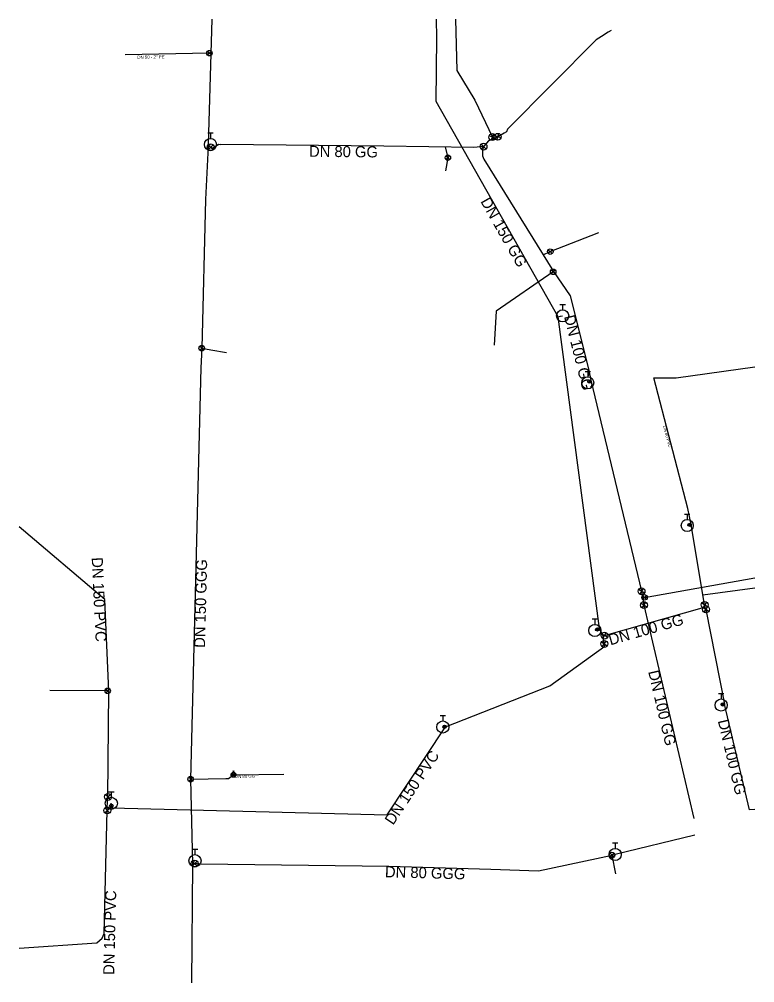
# Model space of a CAD drawing. Extents: x -464830 to -464723, y -1094758 to -1094618.
import ezdxf

# ---------------------------------------------------------------- set-up
doc = ezdxf.new("R2010")
doc.units = 0
for name, color, linetype in [('_hydrantova_odbocka_', 7, 'Continuous'), ('_pripojka_prevzato_z_dokumentace_', 7, 'Continuous'), ('_pripojka_priblizne_', 7, 'Continuous'), ('_voda_smvak_prevzato_z_dokumentace_', 7, 'Continuous'), ('_voda_smvak_priblizne_', 7, 'Continuous'), ('Default', 7, 'Continuous'), ('MoLevel 2', 7, 'Continuous'), ('MoLevel 27', 7, 'Continuous'), ('MoLevel 28', 7, 'Continuous'), ('MoLevel 30', 7, 'Continuous'), ('MoLevel 32', 7, 'Continuous'), ('MoLevel 42', 7, 'Continuous'), ('MoLevel 46', 7, 'Continuous'), ('MoLevel 53', 7, 'Continuous')]:
    doc.layers.add(name, color=color, linetype=linetype)

# ---------------------------------------------------------------- blocks, each defined once
blk = doc.blocks.new('_uzaver_')
at = {"layer": 'Default'}
for p, q in [((-0.000035, -0.000035), (0.000035, 0.000035)), ((0.000035, -0.000035), (-0.000035, 0.000035))]:
    blk.add_line(p, q, dxfattribs=at)
for radius in [0.00005, 0.0000025]:
    blk.add_circle((0, 0), radius, dxfattribs=at)
blk = doc.blocks.new('_uzaver_pripojka_')
at = {"layer": 'Default'}
for p, q in [((-0.000035, -0.000035), (0.000035, 0.000035)), ((0.000035, -0.000035), (-0.000035, 0.000035))]:
    blk.add_line(p, q, dxfattribs=at)
for radius in [0.00005, 0.0000025]:
    blk.add_circle((0, 0), radius, dxfattribs=at)
blk = doc.blocks.new('_hydrant_voda_')
at = {"layer": 'Default'}
for p, q in [((-0.0000225, 0.000095), (0.0000225, 0.000095)), ((0, 0.000095), (0, 0.00005))]:
    blk.add_line(p, q, dxfattribs=at)
blk.add_circle((0, 0), 0.00005, dxfattribs=at)
blk = doc.blocks.new('_sachta_voda_')
at = {"layer": 'Default'}
blk.add_lwpolyline([(-0.00001, 0.000065), (0, 0.000035), (0.00001, 0.000065)], dxfattribs=at)
blk.add_circle((0, 0), 0.000035, dxfattribs=at)
blk = doc.blocks.new('_poklop_voda_')
at = {"layer": 'Default'}
blk.add_circle((0, 0), 0.00002, dxfattribs=at)

msp = doc.modelspace()

# ---------------------------------------------------------------- linework, layer by layer
at = {"layer": '_hydrantova_odbocka_'}
msp.add_line((-464802.46, -1094635.81), (-464802.15, -1094635.8), dxfattribs=at)
for points in [[(-464751.57, -1094660.85), (-464751.25, -1094660.77), (-464750.94, -1094660.71)], [(-464746.83, -1094670.06), (-464747.04, -1094670.25), (-464747.29, -1094670.45)], [(-464732.27, -1094691.01), (-464732.47, -1094691.07), (-464732.82, -1094691.18)], [(-464745.6, -1094706.12), (-464745.89, -1094706.27), (-464746.27, -1094706.43)], [(-464727.43, -1094717.11), (-464727.66, -1094717.17), (-464727.89, -1094717.26)], [(-464767.97, -1094720.43), (-464768.1, -1094720.41), (-464768.35, -1094720.45)], [(-464816.52, -1094732.2), (-464816.55, -1094731.91), (-464816.56, -1094731.54)], [(-464804.77, -1094739.9), (-464804.6, -1094739.89), (-464804.39, -1094739.88)]]:
    msp.add_lwpolyline(points, dxfattribs=at)
at = {"layer": '_pripojka_prevzato_z_dokumentace_'}
for p, q in [((-464802.29, -1094622.54), (-464802.09, -1094622.54)), ((-464803.41, -1094665.4), (-464802.11, -1094665.65)), ((-464743.77, -1094739.06), (-464743.25, -1094741.78))]:
    msp.add_line(p, q, dxfattribs=at)
msp.add_lwpolyline([(-464805.03, -1094728.01), (-464799.93, -1094727.91), (-464799.54, -1094727.91)], dxfattribs=at)
at = {"layer": '_pripojka_priblizne_'}
for p, q in [((-464802.29, -1094622.54), (-464814.54, -1094622.79)), ((-464802.11, -1094665.65), (-464799.8, -1094666.01)), ((-464730.54, -1094701.23), (-464723.01, -1094700.24)), ((-464799.54, -1094727.91), (-464798.79, -1094727.4))]:
    msp.add_line(p, q, dxfattribs=at)
for points in [[(-464768.01, -1094636.16), (-464767.62, -1094637.72), (-464767.96, -1094639.65)], [(-464753.76, -1094651.85), (-464752.74, -1094651.37), (-464745.68, -1094648.61)], [(-464752.26, -1094654.26), (-464752.32, -1094654.31), (-464760.58, -1094660.02), (-464760.88, -1094664.97)], [(-464732.27, -1094691.01), (-464732.76, -1094688.69), (-464737.68, -1094669.72), (-464734.43, -1094669.72), (-464723.01, -1094668.09)], [(-464739.27, -1094701.68), (-464739.03, -1094701.62), (-464723.01, -1094698.77)], [(-464816.9, -1094715.24), (-464817.08, -1094715.19), (-464825.5, -1094715.14)], [(-464798.79, -1094727.4), (-464798.79, -1094727.4), (-464791.46, -1094727.31)]]:
    msp.add_lwpolyline(points, dxfattribs=at)
at = {"layer": '_voda_smvak_prevzato_z_dokumentace_'}
for p, q in [((-464761.14, -1094634.75), (-464761.06, -1094635.01)), ((-464802.47, -1094636.03), (-464802.12, -1094636.21)), ((-464762.37, -1094636.1), (-464762.44, -1094636.11)), ((-464745.6, -1094706.12), (-464751.57, -1094660.85)), ((-464746.83, -1094670.06), (-464739.47, -1094700.73)), ((-464739.47, -1094700.73), (-464739.27, -1094701.68)), ((-464739.27, -1094701.68), (-464739.12, -1094702.74)), ((-464739.12, -1094702.74), (-464731.88, -1094733.73)), ((-464745.04, -1094707.24), (-464745.6, -1094706.12)), ((-464817.14, -1094732.16), (-464817.05, -1094730.62)), ((-464817.14, -1094732.57), (-464817.14, -1094732.16)), ((-464731.72, -1094736.15), (-464743.31, -1094738.97)), ((-464804.76, -1094740.36), (-464804.88, -1094757.61)), ((-464804.76, -1094740.36), (-464804.43, -1094740.3))]:
    msp.add_line(p, q, dxfattribs=at)
for points in [[(-464801.95, -1094617.61), (-464802.09, -1094622.56), (-464802.46, -1094635.81), (-464802.47, -1094636.03)], [(-464751.57, -1094660.85), (-464769.32, -1094629.55), (-464769.23, -1094620.31), (-464769.26, -1094617.61)], [(-464766.51, -1094617.61), (-464766.34, -1094625.05), (-464763.72, -1094629.36), (-464761.14, -1094634.75)], [(-464743.9, -1094619.23), (-464744.33, -1094619.48), (-464745.31, -1094620.13), (-464746.07, -1094620.59), (-464758.95, -1094633.56), (-464759.11, -1094633.95), (-464759.46, -1094634.18), (-464760.37, -1094634.69)], [(-464760.37, -1094634.69), (-464760.89, -1094634.93), (-464761.06, -1094635.01), (-464761.74, -1094635.29), (-464762.3, -1094635.97), (-464762.59, -1094636.52), (-464762.57, -1094637.46), (-464762.39, -1094637.96), (-464752.26, -1094654.26), (-464749.85, -1094657.8), (-464747.18, -1094668.41), (-464746.83, -1094670.06)], [(-464802.47, -1094636.03), (-464802.84, -1094643.81), (-464803.41, -1094665.4), (-464803.52, -1094668.24), (-464805.03, -1094728.01), (-464804.76, -1094740.36), (-464804.76, -1094740.36)], [(-464802.12, -1094636.21), (-464801.78, -1094636.28), (-464800.94, -1094635.75), (-464800.64, -1094635.81)], [(-464762.44, -1094636.11), (-464763.84, -1094636.22), (-464776.92, -1094636.05), (-464800.64, -1094635.81)], [(-464817.05, -1094730.62), (-464816.9, -1094715.24), (-464817.52, -1094701.94), (-464829.94, -1094691.36)], [(-464829.94, -1094752.58), (-464818.67, -1094751.79), (-464817.88, -1094751.12), (-464817.59, -1094750.47), (-464817.14, -1094732.57)], [(-464804.43, -1094740.3), (-464804.06, -1094740.3), (-464803.5, -1094740.31), (-464776.23, -1094740.68), (-464761.39, -1094741.09), (-464754.45, -1094741.33), (-464743.76, -1094739.06), (-464743.3, -1094738.97)]]:
    msp.add_lwpolyline(points, dxfattribs=at)
at = {"layer": '_voda_smvak_priblizne_'}
for p, q in [((-464730.29, -1094702.72), (-464732.27, -1094691.01)), ((-464744.85, -1094707.17), (-464730.29, -1094703.02)), ((-464730.29, -1094703.02), (-464730.29, -1094702.72)), ((-464730.29, -1094703.02), (-464730.1, -1094703.36)), ((-464730.1, -1094703.36), (-464727.43, -1094717.11)), ((-464745.04, -1094707.24), (-464744.85, -1094707.17)), ((-464744.89, -1094708.38), (-464745.04, -1094707.24)), ((-464817.14, -1094732.16), (-464816.52, -1094732.2))]:
    msp.add_line(p, q, dxfattribs=at)
for points in [[(-464816.52, -1094732.2), (-464776.47, -1094733.23), (-464767.97, -1094720.43), (-464752.81, -1094714.45), (-464744.8, -1094708.72), (-464744.89, -1094708.38)], [(-464723.01, -1094732.42), (-464723.77, -1094732.49), (-464727.43, -1094717.11)]]:
    msp.add_lwpolyline(points, dxfattribs=at)

# ---------------------------------------------------------------- block references
at = {"layer": 'MoLevel 27'}
for p, xscale, yscale, rotation in [((-464761.15, -1094634.72), 10000, 9999.999999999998, 115.71448229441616), ((-464760.37, -1094634.69), 10000.000000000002, 10000.000000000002, 28.023028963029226), ((-464747.04, -1094670.25), 5000, 4999.999999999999, -140.10216525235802), ((-464732.47, -1094691.07), 4999.999999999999, 5000, -159.01510216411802), ((-464739.47, -1094700.73), 10000.000000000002, 10000, 103.462471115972), ((-464739.12, -1094702.74), 10000, 10000.000000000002, -76.866043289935), ((-464730.29, -1094702.72), 10000, 10000.000000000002, 99.5936700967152), ((-464730.1, -1094703.36), 10000, 10000.000000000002, -79.02686311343), ((-464745.89, -1094706.27), 5000, 5000, -158.19859051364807), ((-464744.85, -1094707.17), 10000, 10000, 15.912907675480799), ((-464744.89, -1094708.38), 10000, 10000, -80.362461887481), ((-464727.66, -1094717.17), 5000.000000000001, 5000, -153.8384335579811), ((-464817.05, -1094730.62), 10000.000000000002, 10000.000000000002, 89.4659280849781), ((-464817.14, -1094732.57), 10000, 10000, -91.48570138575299), ((-464816.55, -1094731.91), 5000, 5000, 90)]:
    msp.add_blockref('_uzaver_', p, dxfattribs=dict(at, xscale=xscale, yscale=yscale, rotation=rotation))
for p, xscale, yscale in [((-464802.12, -1094636.21), 10000, 10000), ((-464762.44, -1094636.11), 10000, 10000), ((-464768.1, -1094720.41), 5000, 5000), ((-464804.43, -1094740.3), 10000, 10000)]:
    msp.add_blockref('_uzaver_', p, dxfattribs=dict(at, xscale=xscale, yscale=yscale))
at = {"layer": 'MoLevel 28', "xscale": 17636.68430335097, "yscale": 17636.68430335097}
for p in [(-464802.15, -1094635.8), (-464750.94, -1094660.71), (-464747.29, -1094670.45), (-464732.82, -1094691.18), (-464746.27, -1094706.43), (-464727.89, -1094717.26), (-464768.35, -1094720.45), (-464816.56, -1094731.54), (-464804.39, -1094739.88), (-464743.31, -1094738.97)]:
    msp.add_blockref('_hydrant_voda_', p, dxfattribs=at)
at = {"layer": 'MoLevel 30', "xscale": 10000, "yscale": 10000}
msp.add_blockref('_sachta_voda_', (-464798.79, -1094727.4), dxfattribs=at)
at = {"layer": 'MoLevel 42', "xscale": 10000, "yscale": 10000}
msp.add_blockref('_poklop_voda_', (-464798.79, -1094727.4), dxfattribs=at)
at = {"layer": 'MoLevel 53', "xscale": 7999.999999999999, "yscale": 7999.999999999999}
for p in [(-464802.29, -1094622.54), (-464767.62, -1094637.72), (-464752.74, -1094651.37), (-464752.32, -1094654.31), (-464803.41, -1094665.4), (-464739.03, -1094701.62), (-464817.08, -1094715.19), (-464805.03, -1094728.03), (-464743.77, -1094739.06)]:
    msp.add_blockref('_uzaver_pripojka_', p, dxfattribs=at)

# ---------------------------------------------------------------- texts
at = {"layer": 'MoLevel 2'}
for s, rotation, p in [('DN 100 GG', 15.9262, (-464743.99, -1094708.59)), ('DN 100 GG', 283.4137, (-464728.39, -1094719.55)), ('DN 150 PVC', 56.4104, (-464775.59, -1094734.8))]:
    msp.add_text(s, height=1.605, rotation=rotation, dxfattribs=at).set_placement(p)
at = {"layer": 'MoLevel 32'}
for s, rotation, p in [("DN 50 - 2'' PE", 1.1922, (-464812.76, -1094623.36)), ('DN 80 PVC', 284.5478, (-464736.35, -1094676.71)), ('DN 80 GG', 0.6962, (-464798.58, -1094727.85))]:
    msp.add_text(s, height=0.455, rotation=rotation, dxfattribs=at).set_placement(p)
at = {"layer": 'MoLevel 46'}
for s, rotation, p in [('DN 80 GG', 359.4299, (-464787.82, -1094637.59)), ('DN 150 GG', 299.559, (-464762.93, -1094644.07)), ('DN 100 GG', 284.1472, (-464750.75, -1094660.8)), ('DN 150 PVC', 272.6762, (-464819.41, -1094695.82)), ('DN 150 GGG', 88.5528, (-464802.94, -1094708.96)), ('DN 100 GG', 283.1571, (-464738.51, -1094712.4)), ('DN 80 GGG', 358.3948, (-464776.79, -1094742.27)), ('DN 150 PVC', 88.5664, (-464816.14, -1094756.49))]:
    msp.add_text(s, height=1.605, rotation=rotation, dxfattribs=at).set_placement(p)

doc.saveas('drawing.dxf')
